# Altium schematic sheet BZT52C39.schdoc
size 127 x 101 mm
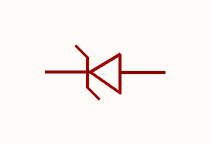
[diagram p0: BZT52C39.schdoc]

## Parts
ZD?  bzt52c39_c2111  [SOD-123_L2.8-W1.8-LS3.7-RD]  (value not drawn)

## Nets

Not connected (* = marked no-connect by the designer): ZD? 1(K) 2(A)

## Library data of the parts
ZD? = bzt52c39_c2111: 二极管配置:1个独立式;稳压值(标称值):39V;稳压值(范围):37V~41V;耗散功率(Pd):500mW;; Manufacturer: CJ(江苏长电/长晶); AddInBom: yes; ModelId: 7884390a25fb4c08947731ebfba7e3f8; ModelTransform: 144.8816,62.992,0,0,0,0,0,0,0; Diode Configuration: 1个独立式; Zener Voltage(Nom): 39V; Reverse Leakage Current (Ir): 100nA; Pd - Power Dissipation: 500mW; Impedance(Zzt): 130Ω; Impedance(Zzk): 350Ω; Operating Junction Temperature Range: -55℃~+150℃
